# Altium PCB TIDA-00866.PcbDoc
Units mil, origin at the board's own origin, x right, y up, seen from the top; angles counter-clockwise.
Board outline 3130 x 2560 mil, 4 copper layers (Top Layer, MidLayer1, MidLayer2, Bottom Layer), stack 92.8 mil thick; 32 components, 7 nets, 46 pads, 43 vias.
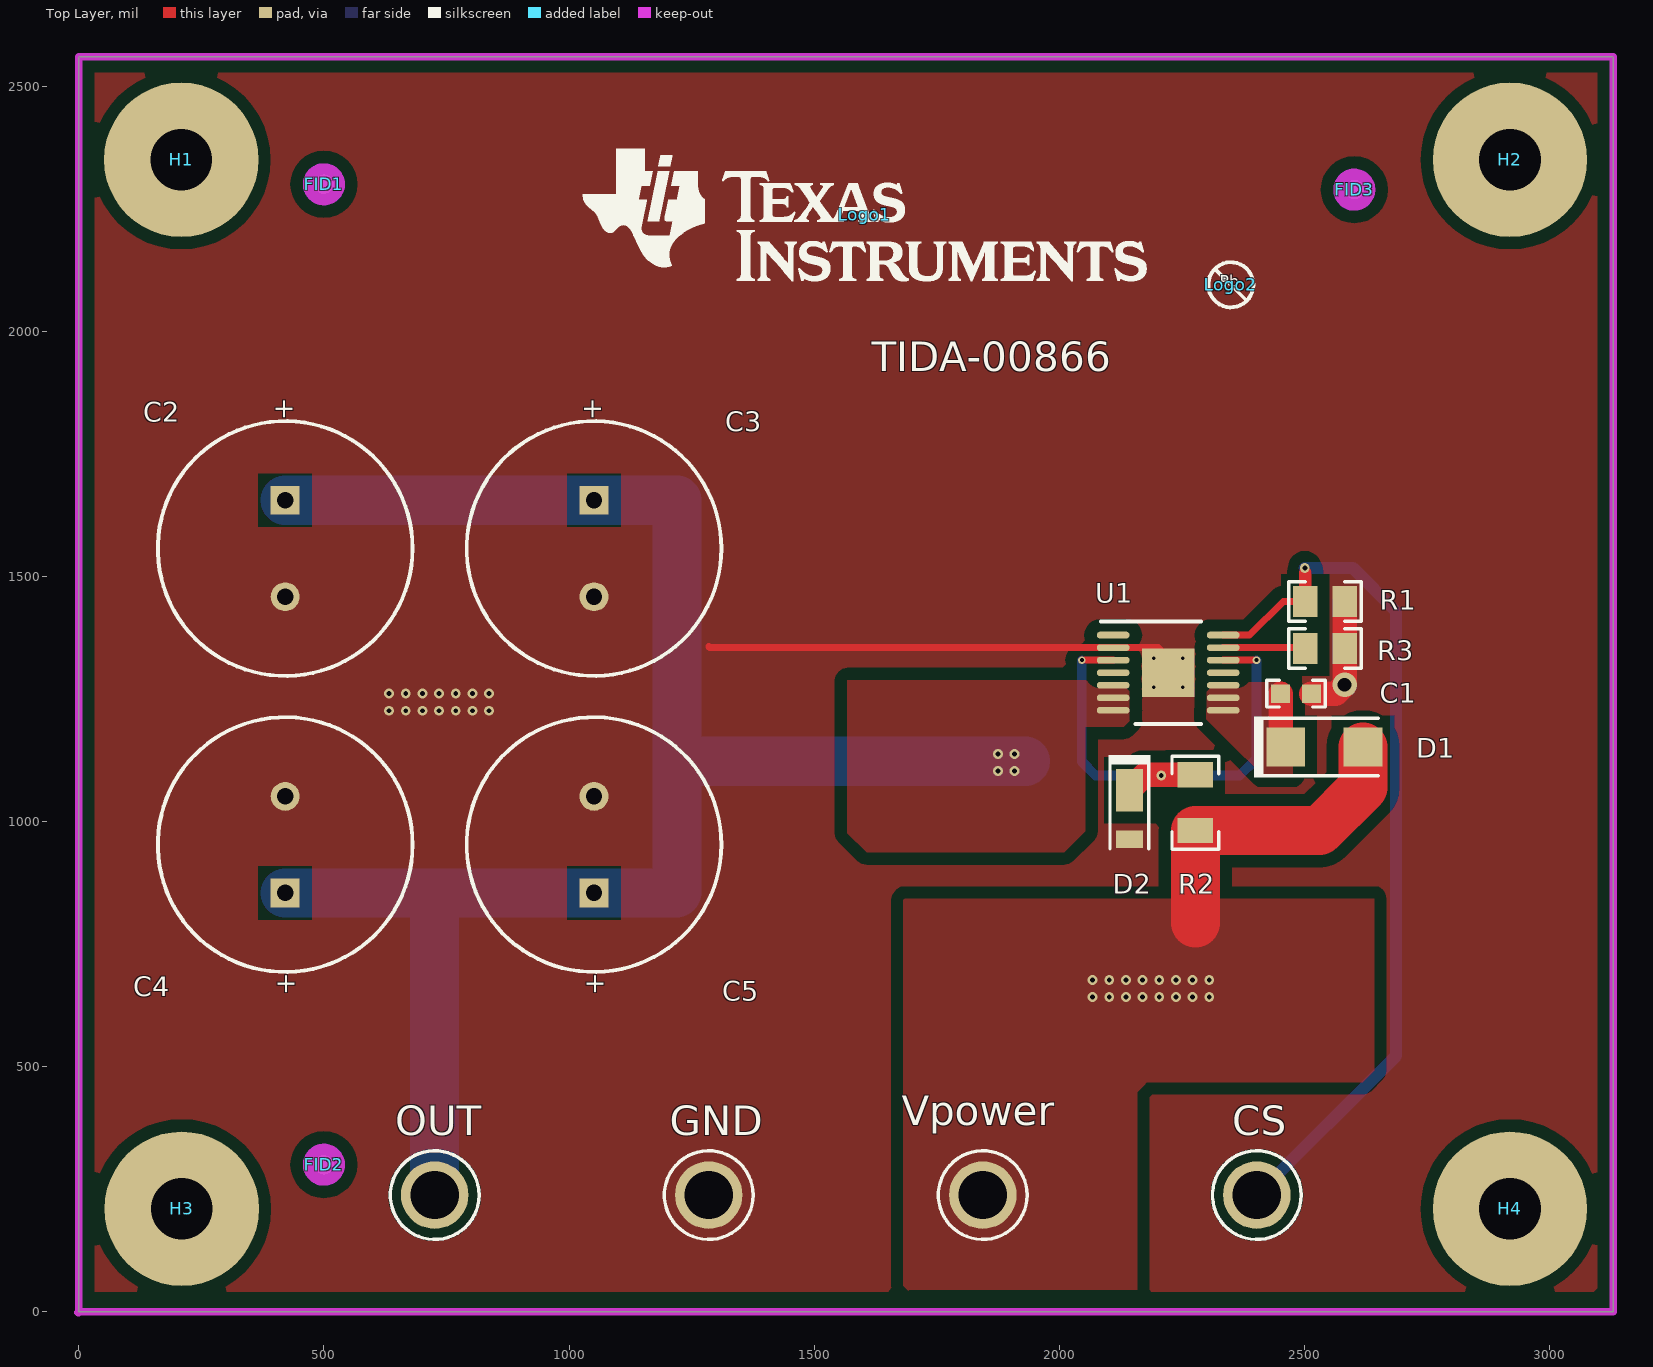
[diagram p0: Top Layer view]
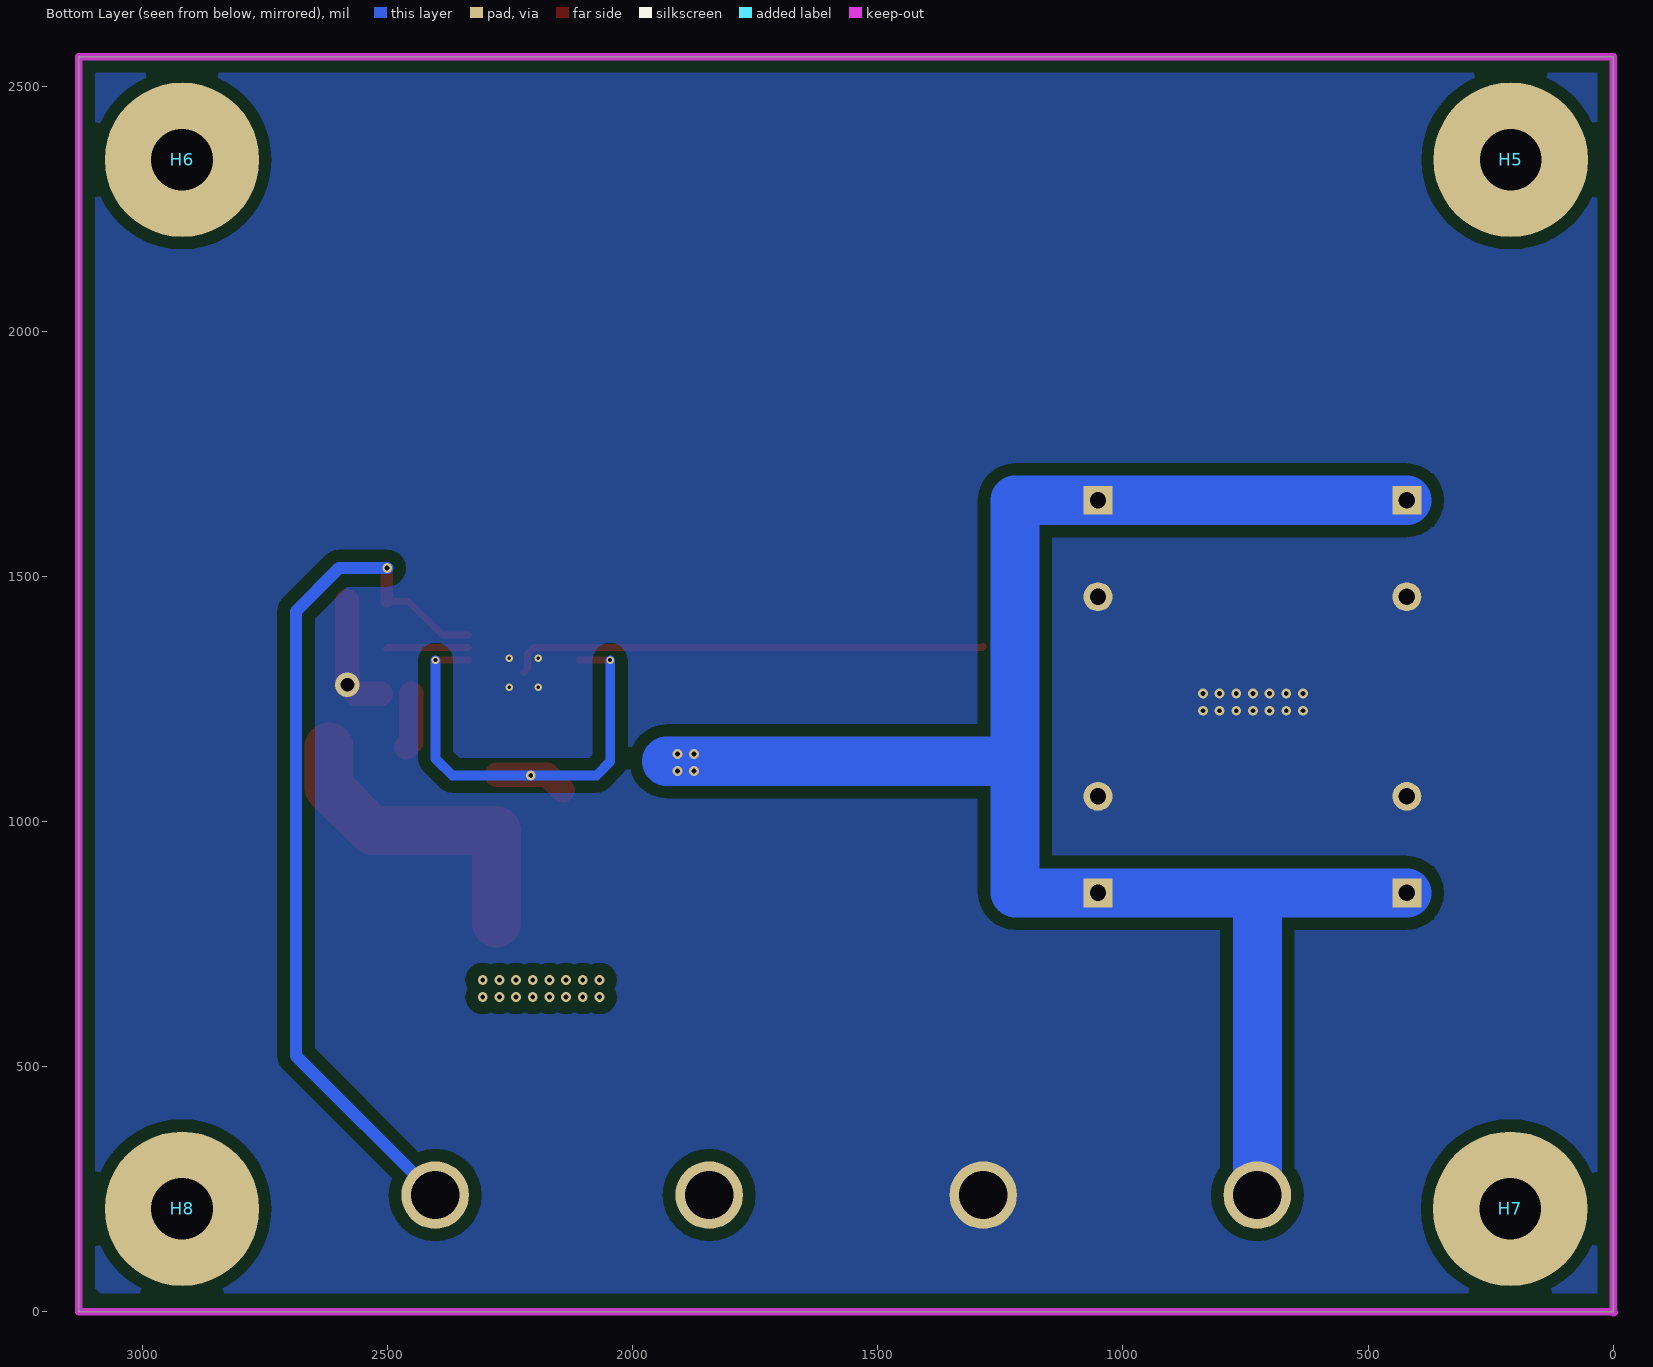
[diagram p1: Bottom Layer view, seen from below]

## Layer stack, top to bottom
Top Solder: solder mask 0.4, Solder Resist, Dk 3.5
Top Layer: signal copper 2.8
Dielectric1: core 59.2, FR-4, Dk 4.8
MidLayer1: signal copper 1.4
Dielectric2: prepreg 12.6, FR-4, Dk 4.8
MidLayer2: signal copper 1.4
Dielectric3: core 12.6, FR-4, Dk 4.8
Bottom Layer: signal copper 2.8
Bottom Solder: solder mask 0.4, Solder Resist, Dk 3.5

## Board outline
0,0 3130,0 3130,2560 0,2560

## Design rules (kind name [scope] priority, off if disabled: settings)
AcuteAngle [All] p1: minimum=4.50000000000000E+0001 checktracksonly=FALSE
AssemblyTestPointUsage [All] p1: valid=2
Clearance Clearance_BoardEdge_MountingHoles [OnCopper and InComponentClass('Mounting Holes') vs IsKeepOut] p1: gap=40
Clearance Clearance_BoardEdge_Poly [OnCopper and InPoly vs IsKeepOut] p2: gap=25
Clearance Clearance_BoardEdge [OnCopper and Not InComponentClass('Logo') and not InComponentClass('FiducialMark') and not InRegion(1000,500,4000,800) and Not IsKeepout vs IsKeepOut] p3: gap=40
Clearance Clearance_Poly [InPolygon] p4: gap=25
Clearance [All] p5: gap=7
ComponentClearance ComponentClearance_Shunt [InComponentClass('Header') vs InComponentClass('Shunt')] p1: gap=0 collisioncheckmode=3 verticalgap=0 showdistances=FALSE
ComponentClearance ComponentClearance_MountingHoles_FiducialMarks [InComponentClass('Mounting Holes') vs InComponentClass('FiducialMark')] p2: gap=50 collisioncheckmode=3 verticalgap=10 showdistances=FALSE
ComponentClearance ComponentClearance_Logo [InComponentClass('Logo')] p3: gap=50 collisioncheckmode=3 verticalgap=10 showdistances=FALSE
ComponentClearance ComponentClearance_ScrewToNut [(HasFootprint('NY PMS 440 0025 PH')) vs (HasFootprint('Keystone_1902C'))] p4: gap=5 collisioncheckmode=3 verticalgap=10 showdistances=FALSE
ComponentClearance ComponentClearance_MountingHoles [InComponentClass('Mounting Holes')] p5: gap=250 collisioncheckmode=3 verticalgap=100000 showdistances=FALSE
ComponentClearance ComponentClearance_SmallPassives [HasFootprint('0201*') or HasFootprint('0402*') or HasFootprint('0508') or HasFootprint('0603*') or HasFootprint('0612') or HasFootprint('0805*') or HasFootprint('0815*') or HasFootprint('0830*') or HasFootprint('1206*') or HasFootprint('1210*') or HasFootprint('1808*') or HasFootprint('1812*') or HasFootprint('1825*') or HasFootprint('2010*') or HasFootprint('2220*') or HasFootprint('2225*') or HasFootprint('2512*') or HasFootprint('2728*') or HasFootprint('3518*') vs HasFootprint('0201*') or HasFootprint('0402*') or HasFootprint('0508') or HasFootprint('0603*') or HasFootprint('0612') or HasFootprint('0805*') or HasFootprint('0815*') or HasFootprint('0830*') or HasFootprint('1206*') or HasFootprint('1210*') or HasFootprint('1808*') or HasFootprint('1812*') or HasFootprint('1825*') or HasFootprint('2010*') or HasFootprint('2220*') or HasFootprint('2225*') or HasFootprint('2512*') or HasFootprint('2728*') or HasFootprint('3518*')] p6: gap=20 collisioncheckmode=3 verticalgap=10 showdistances=FALSE
ComponentClearance ComponentClearance_THtoSMT [IsThruComponent vs IsSMTComponent] p7: gap=20 collisioncheckmode=3 verticalgap=30 showdistances=FALSE
ComponentClearance ComponentClearance_THtoTH [IsThruComponent vs IsThruComponent] p8: gap=30 collisioncheckmode=3 verticalgap=30 showdistances=FALSE
ComponentClearance [All] p9: gap=20 collisioncheckmode=3 verticalgap=10 showdistances=FALSE
DiffPairsRouting [All] p1: maxlimit=100 minlimit=10 mostfreqgap=10 toplayer_minwidth=15 toplayer_maxwidth=15 toplayer_prefwidth=15 midlayer1_minwidth=15 midlayer1_maxwidth=15 midlayer1_prefwidth=15 midlayer2_minwidth=15 midlayer2_maxwidth=15 midlayer2_prefwidth=15 bottomlayer_minwidth=15 bottomlayer_maxwidth=15 bottomlayer_prefwidth=15 maxuncoupledlength=1000
FabricationTestPointUsage TestPointUsage [All] p1: valid=2 allowmultiple=FALSE
FabricationTestpoint Testpoint [All] p1: side=3 testpointundercomponent=TRUE minsize=40 maxsize=100 preferedsize=60 minholesize=0 maxholesize=40 preferedholesize=32 testpointgrid=1 allowsidetop=TRUE allowsidebottom=TRUE usegrid=TRUE gridtolerance=0.01
FanoutControl Fanout_LCC [IsLCC] p1: bgadir=Out bgaviamode=Centered fanoutstyle=Auto fanoutdirection=Alternating viagrid=1 // Fanout_LCC (Default Rule)
FanoutControl Fanout_BGA [IsBGA] p2: bgadir=Out bgaviamode=Centered fanoutstyle=Auto fanoutdirection=Alternating viagrid=1 // Fanout_BGA (Default Rule)
FanoutControl Fanout_Default [All] p4: bgadir=Out bgaviamode=Centered fanoutstyle=Auto fanoutdirection=Alternating viagrid=1 // Fanout_Default (Default Rule)
FanoutControl Fanout_Small [(CompPinCount < 5)] p5: bgadir=Out bgaviamode=Centered fanoutstyle=Auto fanoutdirection=OutThenIn viagrid=1 // Fanout_Small (Default Rule)
HoleSize [All] p1: absolutevalues=TRUE maxlimit=300 minlimit=6 maxpercent=80.000 minpercent=20.000
MinimumAnnularRing MinimumAnnularRing_ThermalPadVias [IsVia and InAnyComponent] p1: minimumring=5
MinimumAnnularRing [All] p2: minimumring=5
MinimumSolderMaskSliver MinimumSolderMaskSliver_Logo [InComponentClass('Logo') vs InComponentClass('Logo')] p1: minsoldermaskwidth=0.7
MinimumSolderMaskSliver [All] p2: minsoldermaskwidth=3.94
PlaneConnect [All] p1: planeconnectstyle=Relief reliefexpansion=10 reliefentries=4 reliefconductorwidth=10 reliefairgap=10
PolygonConnect [All] p1: connectstyle=Direct reliefconductorwidth=10 reliefentries=4 polygonreliefangle="90 Angle" airgapwidth=10
RoutingVias ThermalPadVias [IsVia and InAnyComponent] p1: holewidth=7.87 width=19.68 viastyle="Through Hole" minholewidth=7.87 minwidth=19.68 maxholewidth=12.99 maxwidth=23.62
RoutingVias [All] p2: holewidth=16 width=34 viastyle="Through Hole" minholewidth=5 minwidth=10 maxholewidth=40 maxwidth=65
SMDToCorner [All] p1: distance=30000
SilkToSilkClearance SilkToSilkClearance_Pb-FreeLogo [(HasFootprint('Pb-Free_Overlay_Medium') OR HasFootprint('Pb-Free_Overlay_Small')) vs (HasFootprint('Pb-Free_Overlay_Medium') OR HasFootprint('Pb-Free_Overlay_Small'))] p1: silktosilkclearance=0
SilkToSilkClearance [All] p2: silktosilkclearance=5
SilkToSolderMaskClearance SilkscreenOverComponentPads [IsPad] p1: minsilkscreentomaskgap=5 clearancetoexposedcopper=TRUE
SolderMaskExpansion [All] p1: expansion=1.97
Width [All] p1: maxlimit=100 minlimit=6 preferedwidth=10 checkconnectedcopper=TRUE
16 further rules are at their usual default settings.

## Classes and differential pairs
component class TIDA-00866: C1 C2 C3 C4 C5 CS D1 D2 GND OUT R1 R2 R3 U1 Vpower
component class AssemblyNote: ZZ1 ZZ2 ZZ3 ZZ4
component class FiducialMark: FID1 FID2 FID3
component class TIDA-00866_Hardware_ANSI-B: FID1 FID2 FID3 H1 H2 H3 H4 H5 H6 H7 H8 Logo1 Logo2 ZZ1 ZZ2 ZZ3 ZZ4
component class Logo: Logo1
component class "Mounting Holes": H1 H2 H3 H4

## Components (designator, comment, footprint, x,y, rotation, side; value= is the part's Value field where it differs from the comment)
C1 "GRM188R71H104KA93D" 0603 2483,1261 r180 top
C2 "63ZLH470M12.5X25" ZLH_1250x2500 421,1557 r270 top
C3 "63ZLH470M12.5X25" ZLH_1250x2500 1051,1557 r270 top
C4 "63ZLH470M12.5X25" ZLH_1250x2500 421,953 r90 top
C5 "63ZLH470M12.5X25" ZLH_1250x2500 1051,953 r90 top
CS "Suggest using a net name here" Keystone1502-2 2403,238 r0 top (schematic designator CS_IO)
D1 "B350A-13-F" SMA 2541,1152 r0 top
D2 "DFLZ5V6-7" powerDI123 2143,1014 r270 top
FID1 "Fiducial" Fiducial10-20 500,2300 r0 top
FID2 "Fiducial" Fiducial10-20 500,300 r0 top
FID3 "Fiducial" Fiducial10-20 2602,2289 r0 top
GND "Suggest using a net name here" Keystone1502-2 1285,238 r0 top (schematic designator GND_IO)
H1 "NY PMS 440 0025 PH" "NY PMS 440 0025 PH" 208.95,2350 r0 top locked
H2 "NY PMS 440 0025 PH" "NY PMS 440 0025 PH" 2919.47,2350 r0 top locked
H3 "NY PMS 440 0025 PH" "NY PMS 440 0025 PH" 210,210 r0 top locked
H4 "NY PMS 440 0025 PH" "NY PMS 440 0025 PH" 2919.47,210 r0 top locked
H5 "1902C" Keystone_1902C 208.95,2350 r180 bottom locked
H6 "1902C" Keystone_1902C 2919.47,2350 r180 bottom locked
H7 "1902C" Keystone_1902C 210,210 r180 bottom locked
H8 "1902C" Keystone_1902C 2919.47,210 r180 bottom locked
Logo1 "Texas Instruments" TI_Stacked_Overlay_Medium 1603,2238 r0 top
Logo2 "Pb-Free Symbol" Pb-Free_Overlay_Small 2350,2095 r0 top
OUT "Suggest using a net name here" Keystone1502-2 726,238 r0 top (schematic designator OUT_IO)
R1 "CRCW08051K00FKEA" 0805_HV 2542,1449 r180 top
R2 "CRCW120610K0JNEA" 1206 2277.69,1038.41 r90 top
R3 "CRCW08051K00FKEA" 0805_HV 2542,1353 r180 top
U1 "TPS1H100BQPWPRQ1" PWP0014C_N 2222.31,1303.59 r0 top
Vpower "Suggest using a net name here" Keystone1502-2 1844,238 r0 top (schematic designator Vpower_IO)
ZZ1 "This Assembly Note is for PCB labels only" AssemblyNoteLabel 145,3058 r0 top
ZZ2 "These assemblies are ESD sensitive, ESD precautions shall be observed." AssemblyNote 145,2949.11 r0 top
ZZ3 "These assemblies must be clean and free from flux and all contaminants. Use of no clean flux is not acceptable." AssemblyNote 145,2860.56 r0 top
ZZ4 "These assemblies must comply with workmanship standards IPC-A-610 Class 2, unless otherwise specified." AssemblyNote 145,2772 r0 top

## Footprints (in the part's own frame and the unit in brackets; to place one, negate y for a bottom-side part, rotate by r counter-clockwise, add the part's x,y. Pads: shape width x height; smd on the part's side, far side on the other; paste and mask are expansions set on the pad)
0603 [mm] "0603 from SM-752 data"
  rect 1x0.95 smd: 1(-0.8,0) 2(0.8,0)
  silkscreen extent -1.52,-0.69 1.52,0.69, body extent -0.87,-0.47 0.87,0.47, height 0.85
0805_HV [mil] "0805 with 30mil clearance between pads"
  rect 50x63 smd: 1(-40,0) 2(40,0)
  silkscreen extent -74,-40 74,40, body extent -43,-29 43,29, height 43
1206 [mm] "1206 from SM-752 data"
  rect 1.3x1.85 smd: 1(-1.45,0) 2(1.45,0)
  silkscreen extent -2.4,-1.21 2.4,1.21, body extent -1.7,-0.9 1.7,0.9, height 1.35
AssemblyNote [mil] "Assembly Note"
AssemblyNoteLabel [mil] "Assembly Note for PCB Labels"
Fiducial10-20 [mm]
  round 1 smd mask+0.5: 1(0,0)
  Top Layer keep-out circle w1.178: c0,0 r0.5
Keystone1502-2 [mm] "Double Turret"
  round 3.5 hole 2.5: 1(0,0)
  silkscreen extent -2.3,-2.3 2.3,2.3, body extent -1.6,-1.6 1.59,1.6, height 5.62
Keystone_1902C [mil] "Hex Standoff, 4-40 threaded, nylon"
  body extent -145,-126 146,126, height 501
"NY PMS 440 0025 PH" [mm] "4-40 nylon screw and mounting hole"
  round 8 hole 3.2: 1(0,0)
  body extent -3.3,-3.3 3.3,3.3, height 2.69
Pb-Free_Overlay_Small [mil]
  silkscreen extent -46,-46 46,46
powerDI123 [mm] "Diodes Inc recommended land pattern, document number DS30628 Rev. 6-2"
  rect 2.2x1.4 smd: 1(-1.275,0)
  rect 0.9x1.4 smd: 2(1.275,0)
  silkscreen extent -3.1,-1.09 1.76,1.09, body extent -2.38,-0.97 1.52,0.96, height 1
PWP0014C_N [mm] "TSOP, 14-Leads, Body 5x4.4mm, Pitch 0.65mm, Thermal Pad 3x3 mm, IPC Medium Density"
  oval 1.7x0.35 smd: 1(-2.85,1.95) 2(-2.85,1.3) 3(-2.85,0.65) 4(-2.85,0) 5(-2.85,-0.65) 6(-2.85,-1.3) 7(-2.85,-1.95) 8(2.85,-1.95) 9(2.85,-1.3) 10(2.85,-0.65) 11(2.85,0) 12(2.85,0.65) 13(2.85,1.3) 14(2.85,1.95)
  rect 2.72x2.5 smd: 15(0,0)
  silkscreen extent -3.47,-2.65 1.7,2.65, body extent -3.21,-2.5 3.21,2.5, height 0.99
SMA [mm] "Molded Diode, 2-Leads, Body 4.3x2.6mm, IPC Medium Density, based on OnSemi component dimensions and land pattern"
  rect 2x2 smd: 1(-2,0) 2(2,0)
  silkscreen extent -3.66,-1.57 2.79,1.57, body extent -2.6,-1.3 2.6,1.3, height 2.42
TI_Stacked_Overlay_Medium [mil]
  silkscreen extent -576,-136 576,134
ZLH_1250x2500 [mm] "Rubycon"
  rect 1.5x1.5 hole 0.85: 1(-2.5,0)
  round 1.5 hole 0.85: 2(2.5,0)
  silkscreen extent -6.6,-6.6 6.6,6.6, body extent -6.45,-6.49 6.49,6.49, height 26.51

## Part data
C1: "CAP, CERM, 0.1uF, 50V, +/-10%, X7R, 0603"
C2 C3 C4 C5: "CAP, AL, 470 µF, 63 V, +/- 20%, 0.043 ohm, TH"
CS GND OUT Vpower: library part 1502-2, "Terminal, Turret, TH, Double"
D1: "Diode, Schottky, 50 V, 3 A, SMA"
D2: "Diode, Zener, 5.6 V, 1 W, PowerDI123"
FID1 FID2 FID3: "Fiducial mark.  There is nothing to buy or mount."
H1 H2 H3 H4: "Machine Screw, Round, #4-40 x 1/4, Nylon, Philips panhead"
H5 H6 H7 H8: "Standoff, Hex, 0.5\"L #4-40 Nylon"
Logo1: library part TI_Logo, "Texas Instrument Corporate Signature"
Logo2: library part Pb-Free
R1 R3: "RES, 1.00 k, 1%, 0.125 W, 0805"
R2: "RES, 10 k, 5%, 0.25 W, 1206"
U1: "TPS1H100-Q1 Single Channel Smart High Side Driver, PWP0014C"
ZZ1: library part AssemblyNoteLabel
ZZ2 ZZ3 ZZ4: library part AssemblyNote

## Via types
v1: diameter 20, hole 10, Top Layer to Bottom Layer, 36 vias
v2: diameter 15.75, hole 7.87, Top Layer to Bottom Layer, 4 vias
v3: diameter 16, hole 8, Top Layer to Bottom Layer, 2 vias
v4: diameter 50, hole 28, Top Layer to Bottom Layer, 1 vias

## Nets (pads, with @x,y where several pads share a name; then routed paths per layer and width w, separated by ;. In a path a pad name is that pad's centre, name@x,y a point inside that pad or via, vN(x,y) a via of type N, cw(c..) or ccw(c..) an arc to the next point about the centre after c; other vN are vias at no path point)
GND: C1.1 C2.2 C3.2 C4.2 C5.2 D2.2 GND.1 R1.1 R3.1 U1.2 U1.15 | length 1222.5
  Top Layer w14: 1285,1357 1287.01,1354.99 2201.85,1354.99 2214.66,1342.18 2214.66,1311.24 U1.15
  Top Layer w50: C1.1 2564,1261 v4(2582,1279) R3.1 R1.1
  other v1: 633,1226 667,1226 701,1226 735,1226 769,1226 803,1226 837,1226 633,1261 667,1261 701,1261 735,1261 769,1261 803,1261 837,1261
  other v2: 2192.79,1274.06 2251.84,1274.06 2192.79,1333.12 2251.84,1333.12
NetC1_2: C1.2 D1.1 U1.8 U1.9 U1.10 | length 113.5
  Top Layer w50: C1.2 2451.5,1162.76 D1.1
NetC2_1: C2.1 C3.1 C4.1 C5.1 OUT.1 U1.5 U1.6 U1.7 | length 3728.8
  Bottom Layer w100: C4.1 725,854.57 ; C2.1 C3.1 1220.57,1655.43 1220.57,1132 ; OUT.1 726,853.57 725,854.57 ; 1219.43,854.57 C5.1 725,854.57 ; 1220.57,855.72 1220.57,1132 ; 1931,1123 1229.57,1123 1220.57,1132
  other v1: 1875,1103 1909,1103 1875,1138 1909,1138
NetCS_IO_1: CS.1 R1.2 U1.14 | length 1786
  Top Layer w14: U1.14 2388.36,1380.36 2457,1449 R1.2
  Top Layer w25: R1.2 v1@2502,1508
  Bottom Layer w25: CS.1 2687,522 2687,1429 2599,1517 v1(2501,1517)
NetD2_1: D2.1 R2.2 U1.3 U1.12 | length 1069.5
  Top Layer w14: v3(2046,1329.18) U1.3 ; U1.12 v3(2402.18,1329.18)
  Top Layer w50: D2.1 2174.3,1095.5 R2.2
  Bottom Layer w20: v3(2046,1329.18) 2046,1122 2074,1094 v1(2208,1094) 2368,1094 2402.18,1128.18 v3(2402.18,1329.18)
NetR3_2: R3.2 U1.13 | length 168.2
  Top Layer w14: U1.13 2500.23,1354.77 R3.2
VPOWER: D1.2 R2.1 Vpower.1 | length 649.6
  Top Layer w100: 2277.69,792.69 R2.1 2531.32,981.32 2619.74,1069.74 D1.2
  other v1: 2068,642 2102,642 2136,642 2170,642 2204,642 2238,642 2272,642 2306,642 2068,677 2102,677 2136,677 2170,677 2204,677 2238,677 2272,677 2306,677
pads on no net: FID1.1 FID2.1 FID3.1 H1.1 H2.1 H3.1 H4.1 U1.1 U1.4 U1.11

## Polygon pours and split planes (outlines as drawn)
NetC1_2 on Top Layer "Top Layer-No Net" (solid, pour order 15): 2300,1284 2300,1220 2300,1209 2346,1163 2414,1095 2476,1095 2476,1270 2467,1279 2462,1284 2300,1284
VPOWER on Top Layer "Top Layer-No Net 1" (solid, pour order 16): 1684,842 1682,840 1682,158 1682,53 1692,43 1694,45 2159,45 2159,448 2172,461 2179,468 2469,468 2619,468 2641,490 2643,492 2643,843 1685,843 1682,840
NetC2_1 on Top Layer "Top Layer-No Net 2" (solid, pour order 17): 1568,1288 1568,976 1607,937 1990,937 2010,937 2049,976 2053,980 2053,1193 2131.41,1193 2143.57,1205.17 2143,1205.74 2143,1285 2143,1288 1568,1288
GND on Top Layer "Multi-Layer-No Net" (solid, pour order 20): 163,1486 166,1483 166,1021 1309,1021 1311,1023 1311,1491 173,1491 168,1486
GND on Top Layer "Bottom Layer-No Net" (solid, pour order 19): 27,2538 30,2535 30,41 3090,41 3100,51 3100,2534 3100,2539 3101,2540 3099,2538 29,2538
GND on Bottom Layer "Bottom Layer-No Net" (solid, pour order 18): 23,2535 26,2532 26,38 3086,38 3096,48 3096,2531 3096,2536 3097,2537 3095,2535 25,2535

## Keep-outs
Keep-Out Layer:
  lines w10: -5,0 ccw(c0,0) 0,-5 ; -5,0 ccw(c0,0) 0,-5 ; -5,0 ccw(c0,0) 0,-5 ; -5,0 ccw(c0,0) 0,-5 ; -5,0 ccw(c0,0) 0,-5 ; -5,0 ccw(c0,0) 0,-5
  lines w15: 0,0 3130,0 3130,2560 0,2560 0,0
  text ".Layer_Name" at 577,-858.49 h40

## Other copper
Top Layer:
  text ".Layer_Name" at 577,-858.49 h40
Bottom Layer:
  text ".Layer_Name" at 577,-858.49 h40

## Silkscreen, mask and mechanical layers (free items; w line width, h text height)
Top Overlay:
  text "TIDA-00866" at 1618,1919 h60
  text ".Layer_Name" at 577,-858.49 h40
Bottom Overlay:
  text ".Layer_Name" at 577,-858.49 h40
Top Paste:
  text ".Layer_Name" at 577,-858.49 h40
Bottom Paste:
  text ".Layer_Name" at 577,-858.49 h40
Top Solder:
  text ".Layer_Name" at 577,-858.49 h40
  text ".Layer_Name" at 577,-858.49 h40
Bottom Solder:
  text ".Layer_Name" at 577,-858.49 h40
Drill Guide:
  text ".Layer_Name" at 577,-858.49 h40
M1 Board Outline:
  the board outline again, w15
  text ".Layer_Name" at 577,-858.49 h40
M2 Board Dimensions:
  rectangle: 125,-410.5 500,-285.5
  rectangle: 0,-285.5 125,-160.5
  lines w7: 0,-285.5 1000,-285.5 ; 125,-410.5 125,-160.5 ; 250,-410.5 250,-160.5 ; 500,-410.5 500,-160.5 ; 750,-410.5 750,-160.5 ; 0,-410.5 0,-160.5 1000,-160.5 1000,-410.5 0,-410.5
  text ".Layer_Name" at 577,-858.49 h40
M3 3D STEP Top:
  text ".Layer_Name" at 577,-858.49 h40
M4 3D STEP Bottom:
  text ".Layer_Name" at 577,-858.49 h40
M5 Assembly Top:
  lines w10: -292,-930.17 6308,-930.17 ; -292,-726.83 6310,-726.83 ; -292,-523.5 -292,-1133.5 3713,-1133.5 6310,-1133.5 6310,-523.5 -291.5,-523.5 -291.5,-1133.5 1284,-1133.5 ; 2173,-1133.5 2173,-523.5 ; 3440,-726.83 3440,-523.5 ; 4280,-726.83 4280,-523.5 ; 4902,-1140 4902,-937.17
  text "COMPONENTS MARKED 'DNP' SHOULD NOT BE POPULATED." at 1153.5,-318.5 h40
  text "ASSEMBLY VARIANT:" at 1153,-434 h40
  text ".VariantName" at 2189,-434 h40
  text "PCB VIEWED FROM TOP SIDE" at -228.5,-655.67 h40
  text "BOARD #:" at 2248,-655.67 h40
  text ".PRJ_Number" at 2793.5,-655.67 h40
  text "REV:" at 3638,-655.67 h40
  text ".PCB_Rev" at 3929.5,-655.67 h40
  text "SVN REV:" at 4476,-655.67 h40
  text ".VersionControl_RevNumber" at 4982,-655.67 h40
  text "IGNORE ->" at -228.5,-858.49 h40
  text "PLOT NAME =" at -228.5,-1064.34 h40
  text ".plot_File_Name" at 577,-1064.34 h40
  text "GENERATED    :" at 2250,-1064.34 h40
  text ".Print_Date" at 3119.5,-1064.34 h40
  text ".Print_Time" at 3848.5,-1064.34 h40
  text "TEXAS INSTRUMENTS" at 5113,-1064.34 h40
M6 Assembly Bottom:
  lines w10: -292.5,-727.33 6309.5,-727.33 ; -290.5,-930.67 6309.5,-930.67 ; 1115.5,-1140.5 1115.5,-937.67 ; 1737.5,-727.33 1737.5,-524 ; 2577.5,-727.33 2577.5,-524 ; 3844.5,-1134 3844.5,-524 ; 4733.5,-1134 6309,-1134 6309,-524 -292.5,-524 -292.5,-1134 2304.5,-1134 6309.5,-1134 6309.5,-524
  text "COMPONENTS MARKED 'DNP' SHOULD NOT BE POPULATED." at 6102,-318 h40
  text ".VariantName" at 5058,-434 h40
  text "ASSEMBLY VARIANT:" at 6097,-434 h40
  text ".VersionControl_RevNumber" at 1035.5,-656.17 h40
  text "SVN REV:" at 1541.5,-656.17 h40
  text ".PCB_Rev" at 2088,-656.17 h40
  text "REV:" at 2379.5,-656.17 h40
  text ".PRJ_Number" at 3224,-656.17 h40
  text "BOARD #:" at 3769.5,-656.17 h40
  text "PCB VIEWED FROM BOTTOM SIDE" at 6246,-656.17 h40
  text "IGNORE ->" at 2547.85,-858.49 h40
  text "TEXAS INSTRUMENTS" at 904.5,-1064.84 h40
  text ".Print_Time" at 2169,-1064.84 h40
  text ".Print_Date" at 2898,-1064.84 h40
  text "GENERATED    :" at 3767.5,-1064.84 h40
  text ".plot_File_Name" at 5440.5,-1064.84 h40
  text "PLOT NAME =" at 6246,-1064.84 h40
M9 Title Sheet:
  drawing of 57 lines, arcs and shapes, not listed
  text "1" at 739.84,8036.5 h40
  text "2" at 3235.5,8036.5 h40
  text "3" at 5724.84,8036.5 h40
  text "4" at 8231.51,8036.5 h40
  text "5" at 10730.5,8036.5 h40
  text "6" at 13235.5,8036.5 h40
  text "A" at -416.5,6893.5 h40
  text "A" at 14383.5,6893.5 h40
  text "B" at -416.5,4513.5 h40
  text "B" at 14383.5,4513.5 h40
  text "C" at -416.5,2138.5 h40
  text "C" at 14383.5,2138.5 h40
  text "PROJECT TITLE:" at 11343.5,277.5 h40
  text ".PRJ_Title" at 11393.5,144.17 h40
  text "DESIGNED FOR:" at 11343.5,-23.5 h40
  text ".PRJ_Customer" at 11393.5,-163.5 h40
  text "D" at -416.5,-231.5 h40
  text "D" at 14383.5,-231.5 h40
  text "FILE NAME:" at 11343.5,-323.5 h40
  text ".PCB_File_Name_No_Path" at 11393.5,-443.5 h40
  text "Texas Instruments (TI) and/or its licensors do not warrant the accuracy or completeness of this specification" at 6374,-605.34 h40
  text "ENGINEER:" at 11343.5,-613.5 h40
  text "LAYOUT BY:" at 12848.5,-613.5 h40
  text "or any information contained therein. TI and/or its licensors do not warrant that this design will meet" at 6329.01,-718 h40
  text ".PRJ_Engineer" at 11393.5,-768.49 h40
  text ".PCB_Layout" at 12899,-768.49 h40
  text "the specifications, will be suitable for your application or fit for any particular purpose, or will operate in" at 6329.01,-830.67 h40
  text ".Layer_Name" at 577,-858.49 h40
  text "ALTIUM DESIGNER VERSION:" at 12848.5,-923.5 h40
  text "an implementation. TI and/or its licensors do not warrant that the design is production worthy. You should" at 6329.01,-943.33 h40
  text "completely validate and test your design implementation to confirm the system functionality for your application." at 6374,-1056 h40
  text ".print_Scale" at 11393.5,-1056.83 h40
  text ".Application_BuildNumber" at 12899,-1056.83 h40
  text "1" at 739.84,-1263.5 h40
  text "2" at 3235.5,-1263.5 h40
  text "3" at 5724.84,-1263.5 h40
  text "4" at 8231.51,-1263.5 h40
  text "5" at 10730.5,-1263.5 h40
  text "6" at 13235.5,-1263.5 h40
M10 Fab Notes:
  drawing of 185 lines, arcs and shapes, not listed
  text "DESIGN INFORMATION" at 12381.02,5910 h40
  text "MIN. TRACK WIDTH:" at 11736.46,5730 h40
  text "8" at 12832.7,5730 h40
  text "MIL" at 12987.46,5730 h40
  text "MIN. CLEARANCE:" at 11736.46,5598 h40
  text "0.2" at 12772.7,5598 h40
  text "mm" at 12987.46,5598 h40
  text "MIN. VIA PAD SIZE:" at 11736.46,5466 h40
  text "24" at 12802.71,5466 h40
  text "MIL" at 12987.46,5466 h40
  text "0.05mm (2MIL)" at 12431.46,5324.29 h40
  text "MINIMUM ANNULAR RING" at 11407.23,5320 h40
  text "EXTERNAL" at 13139.46,5320 h40
  text "PER" at 11607.23,5202 h40
  text "IPC-D-275 CLASS 2 LEVEL C" at 11827.23,5202 h40
  text "MIL, HOLES" at 13315.46,5089.71 h40
  text "+/-" at 12923,5089 h40
  text "+/-" at 13777,5089 h40
  text "REGISTRATION TOLERANCES:" at 11407.23,5084 h40
  text "METAL" at 12607,5084 h40
  text "5" at 13183.2,5084 h40
  text "3" at 14016.2,5084 h40
  text "MIL" at 14132.46,5084 h40
  text "MATERIAL:" at 11332.46,4874.54 h40
  text "FR-4 High Tg" at 12318.9,4734.21 h40
  text "FR-408" at 11753.46,4725.64 h40
  text "X" at 12165.46,4725.64 h40
  text "OTHER" at 13241.46,4725.64 h40
  text "62 MIL (1.6mm) +/-10%" at 12073.56,4562.92 h40
  text "THICKNESS:" at 11407.23,4558.64 h40
  text "X" at 11945.4,4558.64 h40
  text "OTHER" at 13358.46,4558.64 h40
  text "TOLERANCE:" at 11407.23,4400.64 h40
  text "X" at 12246.53,4400.64 h40
  text "ANSI IPC-6012 TYPE 3 CLASS 2" at 12433.48,4400.64 h40
  text "OTHER +/-" at 12433.46,4244.64 h40
  text "BOW & TWIST:" at 11407.23,4087.64 h40
  text "X" at 12246.53,4087.64 h40
  text "ANSI IPC-6012 TYPE 3 CLASS 2" at 12433.48,4087.64 h40
  text "OTHER +/-" at 12433.46,3929.13 h40
  text "DRILLING:" at 11332.46,3790.64 h40
  text "REFERENCE:" at 11407.23,3673.64 h40
  text "X" at 12055.46,3673.64 h40
  text "AS SHOWN" at 12242.46,3673.64 h40
  text "X" at 12956.46,3673.64 h40
  text "NC_DRILL FILES" at 13093.46,3673.64 h40
  text "PTH MIN COPPER THICKNESS:" at 11407.23,3515.64 h40
  text "X" at 12757.46,3515.64 h40
  text "1MIL" at 12894.46,3515.64 h40
  text "OTHER" at 13391.46,3515.64 h40
  text "BOARD FINISH:" at 11332.46,3356.64 h40
  text "SILKSCREEN:" at 11487.68,3238.64 h40
  text "X" at 12436.46,3238.64 h40
  text "TOP" at 12562.46,3238.64 h40
  text "X" at 12946.46,3238.64 h40
  text "BOTTOM" at 13073.46,3238.64 h40
  text "SILKSCREEN COLOR:" at 11487.68,3071.64 h40
  text "X" at 12435.42,3071.64 h40
  text "WHITE" at 12562.46,3071.64 h40
  text "OTHER" at 13073.46,3071.64 h40
  text "SOLDER RESIST COLOR:" at 11487.68,2901.64 h40
  text "X" at 12055.42,2742.44 h40
  text "GREEN" at 12182.46,2742.44 h40
  text "BLUE" at 12773.46,2742.44 h40
  text "OTHER" at 13311.46,2742.44 h40
  text "IMMERSION GOLD (ENIG)" at 12393.46,2553.92 h40
  text "ENEPIG" at 13731,2550.64 h40
  text "SURFACE FINISH:" at 11332.46,2549.64 h40
  text "X" at 12206.51,2549.64 h40
  text "IMM. TIN/SILVER OR EQUIV" at 11662,2392.64 h40
  text "OTHER" at 13093.46,2392.64 h40
  text "ARRAY/PANEL:" at 11332.46,2213.64 h40
  text "CUT AND TRIM PER MECH LAYER 1" at 12393.46,2209.35 h40
  text "N.C. ROUTE" at 12393.46,2057.64 h40
  text "X" at 13072.46,2057.64 h40
  text "V. SCORE" at 13259.46,2057.64 h40
  text "CERTIFICATION:" at 11332.46,1920.64 h40
  text "MATERIALS AND WORKMANSHIP FOR ALL PCBS" at 12057.46,1920.64 h40
  text "TO MEET OR EXCEED THE REQUIREMENTS OF:" at 12057.46,1822.64 h40
  text "X" at 11683.96,1686.13 h40
  text "ANSI IPC-A-600F CLASS ->" at 11822.96,1686.13 h40
  text "X" at 13462.02,1686.13 h40
  text "2" at 13580.96,1686.14 h40
  text "1" at 13265.96,1684.64 h40
  text "3" at 13934.96,1684.64 h40
  text "X" at 11686.02,1526.64 h40
  text "UL 94V-0" at 11822.96,1526.64 h40
  text "X" at 12498.02,1526.64 h40
  text "RoHS" at 12634.96,1526.64 h40
  text "OTHER" at 13279.36,1526.64 h40
  text "PER ORDER" at 13676.42,1526.64 h40
  text "ADDITIONAL REQUIREMENTS:" at 11332.46,1385.64 h40
  text "MICROSECTION:" at 11407.23,1270.64 h40
  text "YES" at 12312.96,1270.64 h40
  text "REQUIRED" at 13174.46,1114.49 h40
  text "BARE BOARD ELEC. TEST:" at 11407.23,1111.64 h40
  text "NONE" at 12712.96,1111.64 h40
  text "X" at 13047.46,1111.64 h40
  text "PER ORDER" at 13766.46,1111.64 h40
  text "MANUFACTURER'S UL:" at 11407.23,954.64 h40
  text "RAIL" at 12572.96,950.35 h40
  text "METAL" at 13064.77,950.35 h40
  text "X" at 13440,950 h40
  text "SILK" at 13576.46,950.35 h40
  text ".Layer_Name" at 577,-858.49 h40
M11 Gerber Information:
  lines w10: -292,-930.17 6308,-930.17 ; -292,-726.83 6310,-726.83 ; -292,-523.5 -292,-1133.5 3713,-1133.5 6310,-1133.5 6310,-523.5 -291.5,-523.5 -291.5,-1133.5 1284,-1133.5 ; 2173,-1133.5 2173,-523.5 ; 3440,-726.83 3440,-523.5 ; 4280,-726.83 4280,-523.5 ; 4902,-1140 4902,-937.17
  text "ALL ARTWORK VIEWED FROM TOP SIDE" at -228.5,-655.67 h40
  text "BOARD #:" at 2248,-655.67 h40
  text ".PRJ_Number" at 2793.5,-655.67 h40
  text "REV:" at 3638,-655.67 h40
  text ".PCB_Rev" at 3929.5,-655.67 h40
  text "SVN REV:" at 4476,-655.67 h40
  text ".VersionControl_RevNumber" at 4982,-655.67 h40
  text "LAYER NAME =" at -228.5,-858.49 h40
  text "PLOT NAME =" at -228.5,-1064.34 h40
  text ".plot_File_Name" at 577,-1064.34 h40
  text "GENERATED    :" at 2250,-1064.34 h40
  text ".Print_Date" at 3119.5,-1064.34 h40
  text ".Print_Time" at 3848.5,-1064.34 h40
  text "TEXAS INSTRUMENTS" at 5113,-1064.34 h40
M12 Stackup:
  lines w10: 11060,7405.75 14069,7405.75 ; 11060,7583.85 14069,7583.85 ; 11000,6221 ccw(c11057,6221) 11057,6164 14072,6164 ccw(c14072,6221) 14129,6221 14129,7756 ccw(c14072,7756) 14072,7813 11057,7813 ccw(c11057,7756) 11000,7756 11000,6221
  text "Layer Stack Up Detail for: HVL101A_TPS1H100EVM.PcbDoc" at 11060,7658.62 h40
  text "Layer" at 11060,7517.35 h40
  text "Gerber" at 12139.69,7517.35 h40
  text "Copper" at 12671.08,7517.35 h40
  text "Dielectric" at 13269.43,7517.35 h40
  text "Name" at 11060,7435.35 h40
  text "Document" at 12139.69,7435.35 h40
  text "Thickness" at 12671.08,7435.35 h40
  text "Material" at 13269.43,7435.35 h40
  text "Top Solder Mask" at 11060,7314.35 h40
  text "(.GTS)" at 12139.69,7314.35 h40
  text "Solder Resist" at 13269.43,7314.35 h40
  text "Top Layer" at 11060,7141.56 h40
  text "(.GTL)" at 12139.69,7141.56 h40
  text "2.8mil" at 12671.08,7141.56 h40
  text "FR-4" at 13269.43,7055.17 h40
  text "MidLayer1" at 11060,6968.77 h40
  text "(.G1)" at 12139.69,6968.77 h40
  text "1.4mil" at 12671.08,6968.77 h40
  text "FR-4" at 13269.43,6882.38 h40
  text "MidLayer2" at 11060,6795.98 h40
  text "(.G2)" at 12139.69,6795.98 h40
  text "1.4mil" at 12671.08,6795.98 h40
  text "FR-4" at 13269.43,6709.58 h40
  text "Bottom Layer" at 11060,6623.19 h40
  text "(.GBL)" at 12139.69,6623.19 h40
  text "2.8mil" at 12671.08,6623.19 h40
  text "Bottom Solder Mask" at 11060,6450.4 h40
  text "(.GBS)" at 12139.69,6450.4 h40
  text "Solder Resist" at 13269.43,6450.4 h40
  text ".Layer_Name" at 577,-858.49 h40
M13 Component Bodies Top:
  text ".Layer_Name" at 577,-858.49 h40
M14 Component Bodies Bottom:
  text ".Layer_Name" at 577,-858.49 h40
M15 Courtyards Top:
  text ".Layer_Name" at 577,-858.49 h40
M16 Courtyards Bottom:
  text ".Layer_Name" at 577,-858.49 h40
Drill Drawing:
  text ".legend" at 3760,570 h40
  text "Drill Table" at 3750,400 h40
  text ".Layer_Name" at 577,-858.49 h40

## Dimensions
0,-410.5 to 1000,-410.5 on M2 Board Dimensions
0,0 to 3130,0 on M2 Board Dimensions
0,0 to 0,2560 on M2 Board Dimensions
